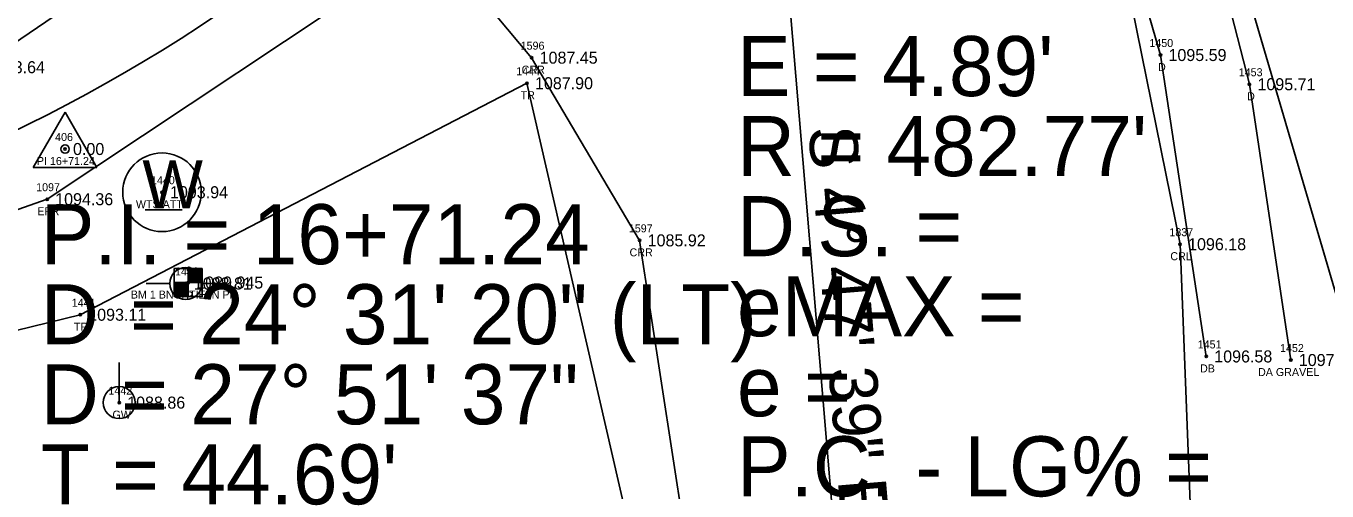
# Model space of a CAD drawing. Extents: x 1539151 to 1541799, y 1198646 to 1201165.
# Drawn here: x 1540056.1 to 1540218.7, y 1199362.7 to 1199420.8 of the extents above; entities that cross this region are included whole.
import ezdxf

# ---------------------------------------------------------------- set-up
doc = ezdxf.new("R2010")
doc.units = 0
for name, color, linetype in [('RD_EX_Driveway', 7, 'Continuous'), ('RD_EX_Driveway_txCode', 7, 'Continuous'), ('RD_EX_H2O', 7, 'Continuous'), ('RD_EX_H2O_txCode', 7, 'Continuous'), ('RD_EX_Road', 7, 'Continuous'), ('RD_EX_Road_txCode', 7, 'Continuous'), ('RD_EX_TX_Driveway_ELEV', 7, 'Continuous'), ('RD_EX_TX_H2O_ELEV', 7, 'Continuous'), ('RD_EX_TX_Road_ELEV', 7, 'Continuous'), ('RD_EX_TX_UT_ELEV', 7, 'Continuous'), ('RD_EX_TX_VEG_ELEV', 7, 'Continuous'), ('RD_EX_UT', 7, 'Continuous'), ('RD_EX_UT_txCode', 7, 'Continuous'), ('RD_EX_VEG', 7, 'Continuous'), ('RD_EX_VEG_txCode', 7, 'Continuous'), ('RD_HC_Cl', 7, 'Continuous'), ('RD_HC_Data', 7, 'Continuous'), ('RD_HC_Survey', 7, 'Continuous'), ('RD_HC_Survey_ELEV', 7, 'Continuous'), ('RD_HC_Survey_txCode', 7, 'Continuous'), ('RD_HC_txCode', 7, 'Continuous'), ('RD_SMD_Locator', 7, 'Continuous')]:
    doc.layers.add(name, color=color, linetype=linetype)

msp = doc.modelspace()

# ---------------------------------------------------------------- linework, layer by layer
at = {"layer": 'RD_EX_Driveway'}
for points in [[(1540214.21, 1199379.03), (1540209.04, 1199413.48), (1540199.66, 1199449.96), (1540186.8, 1199484.99), (1540182.78, 1199498.31), (1540181.23, 1199508.28)], [(1540167.88, 1199484.64), (1540174.25, 1199480.46), (1540187.6, 1199452.87), (1540197.92, 1199417.13), (1540203.64, 1199379.48)]]:
    msp.add_lwpolyline(points, dxfattribs=at)
at = {"layer": 'RD_EX_H2O'}
for points in [[(1540167.88, 1199484.64), (1540176.46, 1199458.2), (1540182.66, 1199452.12), (1540193.19, 1199429.05), (1540200.37, 1199393.5), (1540202.4, 1199340.71), (1540198.55, 1199306.73), (1540179.64, 1199280.12), (1540151.78, 1199264.65), (1540144.74, 1199262.14), (1540137.88, 1199248.47), (1540155.53, 1199232.49), (1540156.47, 1199194.6), (1540144.81, 1199166.15), (1540127.69, 1199133.28), (1540119.65, 1199099.79), (1540112.02, 1199051.08), (1540113.69, 1199004.24), (1540113.12, 1198937.28), (1540119.39, 1198871.63)], [(1540110.32, 1199427.56), (1540119.33, 1199416.8), (1540132.83, 1199393.98), (1540138.31, 1199358.3), (1540135.73, 1199340.81)]]:
    msp.add_lwpolyline(points, dxfattribs=at)
at = {"layer": 'RD_EX_Road'}
for points in [[(1539428.76, 1199454.93), (1539416.46, 1199395.23), (1539420.91, 1199377.84), (1539428.29, 1199368.53), (1539440.24, 1199363.06), (1539462.84, 1199364.11), (1539506.12, 1199366.59), (1539554.03, 1199368.02), (1539606.53, 1199370.48), (1539651.89, 1199372.76), (1539672.94, 1199372.91), (1539707.02, 1199374.85), (1539748.7, 1199377.62), (1539769.05, 1199378.19), (1539812.94, 1199380.16), (1539830.48, 1199381.23), (1539857.01, 1199382.87), (1539908.22, 1199385.45), (1539955.82, 1199389.74), (1539996.13, 1199397.4), (1540037.85, 1199410.51), (1540050.26, 1199415.61), (1540093.12, 1199444.78)], [(1539925.86, 1199367.85), (1539963.35, 1199372.53), (1539983.91, 1199375.76), (1540009.01, 1199381.59), (1540058.79, 1199399.12), (1540106.31, 1199430.72)]]:
    msp.add_lwpolyline(points, dxfattribs=at)
at = {"layer": 'RD_EX_UT'}
for p, q in [((1540071.02, 1199397.78), (1540075.65, 1199397.78)), ((1540071.18, 1199388.61), (1540074.11, 1199388.61)), ((1540078.11, 1199388.61), (1540081.18, 1199388.61)), ((1540067.79, 1199373.71), (1540067.79, 1199378.71))]:
    msp.add_line(p, q, dxfattribs=at)
for centre, radius in [((1540073.14, 1199399.99), 4.91), ((1540076.11, 1199388.59), 2), ((1540067.79, 1199373.71), 2)]:
    msp.add_circle(centre, radius, dxfattribs=at)
at = {"layer": 'RD_EX_VEG'}
for points in [[(1540836.37, 1200082.45), (1540794.45, 1200101.71), (1540758.65, 1200106.39), (1540697.29, 1200033.83), (1540560.39, 1199886.45), (1540422.51, 1199739.87), (1540382.08, 1199704.72), (1540267.52, 1199610.92), (1540233.68, 1199579.65), (1540209.33, 1199537.96), (1540187.75, 1199496.51), (1540221.64, 1199381.22)], [(1539913.28, 1199258.8), (1539924.81, 1199358.8), (1539963.86, 1199360.44), (1540062.92, 1199384.69), (1540118.75, 1199413.61), (1540135.27, 1199341.7), (1540089.61, 1199284.74)]]:
    msp.add_lwpolyline(points, dxfattribs=at)
at = {"layer": 'RD_HC_Cl'}
msp.add_line((1540150.21, 1199440.05), (1540160.06, 1199322.6), dxfattribs=at)
msp.add_arc((1539965.21, 1199592.77), 205.65, 284.8221, 309.3443, dxfattribs=at)
at = {"layer": 'RD_HC_Data'}
for p, q in [((1540057.05, 1199403.1), (1540061.03, 1199409.98)), ((1540061.03, 1199409.98), (1540064.99, 1199403.1)), ((1540057.05, 1199403.1), (1540064.99, 1199403.1))]:
    msp.add_line(p, q, dxfattribs=at)
msp.add_circle((1540061.02, 1199405.39), 0.529, dxfattribs=at)
at = {"layer": 'RD_HC_Survey'}
for p, q in [((1540076.42, 1199390.46), (1540076.42, 1199386.96)), ((1540076.44, 1199390.46), (1540076.44, 1199388.71)), ((1540076.46, 1199390.46), (1540076.46, 1199388.71)), ((1540076.49, 1199390.46), (1540076.49, 1199388.71)), ((1540076.51, 1199390.46), (1540076.51, 1199388.71)), ((1540076.54, 1199390.46), (1540076.54, 1199388.71)), ((1540076.56, 1199390.46), (1540076.56, 1199388.71)), ((1540076.59, 1199390.46), (1540076.59, 1199388.71)), ((1540076.61, 1199390.46), (1540076.61, 1199388.71)), ((1540076.64, 1199390.46), (1540076.64, 1199388.71)), ((1540076.66, 1199390.46), (1540076.66, 1199388.71)), ((1540076.69, 1199390.46), (1540076.69, 1199388.71)), ((1540076.71, 1199390.46), (1540076.71, 1199388.71)), ((1540076.74, 1199390.46), (1540076.74, 1199388.71)), ((1540076.76, 1199390.46), (1540076.76, 1199388.71)), ((1540076.79, 1199390.46), (1540076.79, 1199388.71)), ((1540076.81, 1199390.46), (1540076.81, 1199388.71)), ((1540076.83, 1199390.46), (1540076.83, 1199388.71)), ((1540076.86, 1199390.46), (1540076.86, 1199388.71)), ((1540076.88, 1199390.46), (1540076.88, 1199388.71)), ((1540076.91, 1199390.46), (1540076.91, 1199388.71)), ((1540076.93, 1199390.46), (1540076.93, 1199388.71)), ((1540076.96, 1199390.46), (1540076.96, 1199388.71)), ((1540076.98, 1199390.46), (1540076.98, 1199388.71)), ((1540077.01, 1199390.46), (1540077.01, 1199388.71)), ((1540077.03, 1199390.46), (1540077.03, 1199388.71)), ((1540077.06, 1199390.46), (1540077.06, 1199388.71)), ((1540077.08, 1199390.46), (1540077.08, 1199388.71)), ((1540077.11, 1199390.46), (1540077.11, 1199388.71)), ((1540077.13, 1199390.46), (1540077.13, 1199388.71)), ((1540077.16, 1199390.46), (1540077.16, 1199388.71)), ((1540077.18, 1199390.46), (1540077.18, 1199388.71)), ((1540077.21, 1199390.46), (1540077.21, 1199388.71)), ((1540077.23, 1199390.46), (1540077.23, 1199388.71)), ((1540077.26, 1199390.46), (1540077.26, 1199388.71)), ((1540077.28, 1199390.46), (1540077.28, 1199388.71)), ((1540077.3, 1199390.46), (1540077.3, 1199388.71)), ((1540077.33, 1199390.46), (1540077.33, 1199388.71)), ((1540077.35, 1199390.46), (1540077.35, 1199388.71)), ((1540077.38, 1199390.46), (1540077.38, 1199388.71)), ((1540077.4, 1199390.46), (1540077.4, 1199388.71)), ((1540077.43, 1199390.46), (1540077.43, 1199388.71)), ((1540077.45, 1199390.46), (1540077.45, 1199388.71)), ((1540077.48, 1199390.46), (1540077.48, 1199388.71)), ((1540077.5, 1199390.46), (1540077.5, 1199388.71)), ((1540077.53, 1199390.46), (1540077.53, 1199388.71)), ((1540077.55, 1199390.46), (1540077.55, 1199388.71)), ((1540077.58, 1199390.46), (1540077.58, 1199388.71)), ((1540077.6, 1199390.46), (1540077.6, 1199388.71)), ((1540077.63, 1199390.46), (1540077.63, 1199388.71)), ((1540077.65, 1199390.46), (1540077.65, 1199388.71)), ((1540077.68, 1199390.46), (1540077.68, 1199388.71)), ((1540077.7, 1199390.46), (1540077.7, 1199388.71)), ((1540077.73, 1199390.46), (1540077.73, 1199388.71)), ((1540077.75, 1199390.46), (1540077.75, 1199388.71)), ((1540077.78, 1199390.46), (1540077.78, 1199388.71)), ((1540077.8, 1199390.46), (1540077.8, 1199388.71)), ((1540077.82, 1199390.46), (1540077.82, 1199388.71)), ((1540077.85, 1199390.46), (1540077.85, 1199388.71)), ((1540077.87, 1199390.46), (1540077.87, 1199388.71)), ((1540077.9, 1199390.46), (1540077.9, 1199388.71)), ((1540077.92, 1199390.46), (1540077.92, 1199388.71)), ((1540077.95, 1199390.46), (1540077.95, 1199388.71)), ((1540077.97, 1199390.46), (1540077.97, 1199388.71)), ((1540078, 1199390.46), (1540078, 1199388.71)), ((1540078.02, 1199390.46), (1540078.02, 1199388.71)), ((1540078.05, 1199390.46), (1540078.05, 1199388.71)), ((1540078.07, 1199390.46), (1540078.07, 1199388.71)), ((1540078.1, 1199390.46), (1540078.1, 1199388.71)), ((1540078.12, 1199390.46), (1540078.12, 1199388.71)), ((1540078.15, 1199390.46), (1540078.15, 1199388.71)), ((1540078.17, 1199388.71), (1540074.67, 1199388.71)), ((1540074.67, 1199388.71), (1540074.67, 1199386.96)), ((1540074.7, 1199388.71), (1540074.7, 1199386.96)), ((1540074.72, 1199388.71), (1540074.72, 1199386.96)), ((1540074.75, 1199388.71), (1540074.75, 1199386.96)), ((1540074.77, 1199388.71), (1540074.77, 1199386.96)), ((1540074.79, 1199388.71), (1540074.79, 1199386.96)), ((1540074.82, 1199388.71), (1540074.82, 1199386.96)), ((1540074.84, 1199388.71), (1540074.84, 1199386.96)), ((1540074.87, 1199388.71), (1540074.87, 1199386.96)), ((1540074.89, 1199388.71), (1540074.89, 1199386.96)), ((1540074.92, 1199388.71), (1540074.92, 1199386.96)), ((1540074.94, 1199388.71), (1540074.94, 1199386.96)), ((1540074.97, 1199388.71), (1540074.97, 1199386.96)), ((1540074.99, 1199388.71), (1540074.99, 1199386.96)), ((1540075.02, 1199388.71), (1540075.02, 1199386.96)), ((1540075.04, 1199388.71), (1540075.04, 1199386.96)), ((1540075.07, 1199388.71), (1540075.07, 1199386.96)), ((1540075.09, 1199388.71), (1540075.09, 1199386.96)), ((1540075.12, 1199388.71), (1540075.12, 1199386.96)), ((1540075.14, 1199388.71), (1540075.14, 1199386.96)), ((1540075.17, 1199388.71), (1540075.17, 1199386.96)), ((1540075.19, 1199388.71), (1540075.19, 1199386.96)), ((1540075.22, 1199388.71), (1540075.22, 1199386.96)), ((1540075.24, 1199388.71), (1540075.24, 1199386.96)), ((1540075.27, 1199388.71), (1540075.27, 1199386.96)), ((1540075.29, 1199388.71), (1540075.29, 1199386.96)), ((1540075.31, 1199388.71), (1540075.31, 1199386.96)), ((1540075.34, 1199388.71), (1540075.34, 1199386.96)), ((1540075.36, 1199388.71), (1540075.36, 1199386.96)), ((1540075.39, 1199388.71), (1540075.39, 1199386.96)), ((1540075.41, 1199388.71), (1540075.41, 1199386.96)), ((1540075.44, 1199388.71), (1540075.44, 1199386.96)), ((1540075.46, 1199388.71), (1540075.46, 1199386.96)), ((1540075.49, 1199388.71), (1540075.49, 1199386.96)), ((1540075.51, 1199388.71), (1540075.51, 1199386.96)), ((1540075.54, 1199388.71), (1540075.54, 1199386.96)), ((1540075.56, 1199388.71), (1540075.56, 1199386.96)), ((1540075.59, 1199388.71), (1540075.59, 1199386.96)), ((1540075.61, 1199388.71), (1540075.61, 1199386.96)), ((1540075.64, 1199388.71), (1540075.64, 1199386.96)), ((1540075.66, 1199388.71), (1540075.66, 1199386.96)), ((1540075.69, 1199388.71), (1540075.69, 1199386.96)), ((1540075.71, 1199388.71), (1540075.71, 1199386.96)), ((1540075.74, 1199388.71), (1540075.74, 1199386.96)), ((1540075.76, 1199388.71), (1540075.76, 1199386.96)), ((1540075.78, 1199388.71), (1540075.78, 1199386.96)), ((1540075.81, 1199388.71), (1540075.81, 1199386.96)), ((1540075.83, 1199388.71), (1540075.83, 1199386.96)), ((1540075.86, 1199388.71), (1540075.86, 1199386.96)), ((1540075.88, 1199388.71), (1540075.88, 1199386.96)), ((1540075.91, 1199388.71), (1540075.91, 1199386.96)), ((1540075.93, 1199388.71), (1540075.93, 1199386.96)), ((1540075.96, 1199388.71), (1540075.96, 1199386.96)), ((1540075.98, 1199388.71), (1540075.98, 1199386.96)), ((1540076.01, 1199388.71), (1540076.01, 1199386.96)), ((1540076.03, 1199388.71), (1540076.03, 1199386.96)), ((1540076.06, 1199388.71), (1540076.06, 1199386.96)), ((1540076.08, 1199388.71), (1540076.08, 1199386.96)), ((1540076.11, 1199388.71), (1540076.11, 1199386.96)), ((1540076.13, 1199388.71), (1540076.13, 1199386.96)), ((1540076.16, 1199388.71), (1540076.16, 1199386.96)), ((1540076.18, 1199388.71), (1540076.18, 1199386.96)), ((1540076.21, 1199388.71), (1540076.21, 1199386.96)), ((1540076.23, 1199388.71), (1540076.23, 1199386.96)), ((1540076.26, 1199388.71), (1540076.26, 1199386.96)), ((1540076.28, 1199388.71), (1540076.28, 1199386.96)), ((1540076.3, 1199388.71), (1540076.3, 1199386.96)), ((1540076.33, 1199388.71), (1540076.33, 1199386.96)), ((1540076.35, 1199388.71), (1540076.35, 1199386.96)), ((1540076.38, 1199388.71), (1540076.38, 1199386.96)), ((1540076.4, 1199388.71), (1540076.4, 1199386.96))]:
    msp.add_line(p, q, dxfattribs=at)
msp.add_lwpolyline([(1540078.17, 1199390.46), (1540074.67, 1199390.46), (1540074.67, 1199386.96), (1540078.17, 1199386.96)], close=True, dxfattribs=at)
at = {"layer": 'RD_SMD_Locator'}
for centre in [(1540119.33, 1199416.8), (1540197.92, 1199417.13), (1540118.75, 1199413.61), (1540209.04, 1199413.48), (1540061.02, 1199405.39), (1540058.79, 1199399.12), (1540073.14, 1199399.99), (1540132.83, 1199393.98), (1540200.37, 1199393.5), (1540076.11, 1199388.59), (1540076.42, 1199388.71), (1540062.92, 1199384.69), (1540203.64, 1199379.48), (1540214.21, 1199379.03), (1540067.79, 1199373.71)]:
    msp.add_circle(centre, 0.15, dxfattribs=at)

# ---------------------------------------------------------------- texts
at = {"layer": 'RD_EX_Driveway_txCode'}
for s, p in [('1450', (1540196.53, 1199418.13)), ('D', (1540197.61, 1199415.13)), ('1453', (1540207.7, 1199414.48)), ('D', (1540208.74, 1199411.48)), ('1451', (1540202.57, 1199380.48)), ('1452', (1540212.86, 1199380.03)), ('DB', (1540202.86, 1199377.48)), ('DA GRAVEL', (1540210.11, 1199377.03))]:
    msp.add_text(s, height=1, dxfattribs=at).set_placement(p)
at = {"layer": 'RD_EX_H2O_txCode'}
for s, p in [('1596', (1540117.96, 1199417.8)), ('CRR', (1540118.08, 1199414.8)), ('1597', (1540131.48, 1199394.98)), ('1837', (1540199.03, 1199394.5)), ('CRR', (1540131.57, 1199391.98)), ('CRL', (1540199.15, 1199391.5))]:
    msp.add_text(s, height=1, dxfattribs=at).set_placement(p)
at = {"layer": 'RD_EX_Road_txCode'}
for s, p in [('1097', (1540057.41, 1199400.12)), ('EPR', (1540057.56, 1199397.12))]:
    msp.add_text(s, height=1, dxfattribs=at).set_placement(p)
at = {"layer": 'RD_EX_TX_Driveway_ELEV'}
for s, p in [('1095.59', (1540198.92, 1199416.38)), ('1095.71', (1540210.04, 1199412.73)), ('1096.58', (1540204.64, 1199378.73)), ('1097.29', (1540215.21, 1199378.28))]:
    msp.add_text(s, height=1.5, dxfattribs=at).set_placement(p)
at = {"layer": 'RD_EX_TX_H2O_ELEV'}
for s, p in [('1087.45', (1540120.33, 1199416.05)), ('1085.92', (1540133.83, 1199393.23)), ('1096.18', (1540201.37, 1199392.75))]:
    msp.add_text(s, height=1.5, dxfattribs=at).set_placement(p)
at = {"layer": 'RD_EX_TX_Road_ELEV'}
for s, p in [('1093.64', (1540051.26, 1199414.86)), ('1094.36', (1540059.79, 1199398.37))]:
    msp.add_text(s, height=1.5, dxfattribs=at).set_placement(p)
at = {"layer": 'RD_EX_TX_UT_ELEV'}
for s, p in [('1093.94', (1540074.14, 1199399.24)), ('1088.81', (1540077.11, 1199387.84)), ('1088.86', (1540068.79, 1199372.96))]:
    msp.add_text(s, height=1.5, dxfattribs=at).set_placement(p)
at = {"layer": 'RD_EX_TX_VEG_ELEV'}
for s, p in [('1087.90', (1540119.75, 1199412.86)), ('1093.11', (1540063.92, 1199383.94))]:
    msp.add_text(s, height=1.5, dxfattribs=at).set_placement(p)
at = {"layer": 'RD_EX_UT'}
msp.add_text('W', height=6, dxfattribs=at).set_placement((1540070.68, 1199397.99))
at = {"layer": 'RD_EX_UT_txCode'}
for s, p in [('1440', (1540071.76, 1199400.99)), ('WTS ATT', (1540069.88, 1199397.99)), ('1443', (1540074.77, 1199389.59)), ('TP', (1540075.32, 1199386.59)), ('1442', (1540066.44, 1199374.71)), ('GW', (1540066.95, 1199371.71))]:
    msp.add_text(s, height=1, dxfattribs=at).set_placement(p)
at = {"layer": 'RD_EX_VEG_txCode'}
for s, p in [('1444', (1540117.41, 1199414.61)), ('TR', (1540117.96, 1199411.61)), ('1441', (1540061.86, 1199385.69)), ('TR', (1540062.13, 1199382.69))]:
    msp.add_text(s, height=1, dxfattribs=at).set_placement(p)
at = {"layer": 'RD_HC_Data'}
for s, p in [("E = 4.89'", (1540145, 1199412)), ("R = 482.77'", (1540145, 1199402)), ('D.S. = ', (1540145, 1199392)), ('P.I. = 16+71.24', (1540058, 1199391)), ('eMAX = ', (1540145, 1199382)), ('D', (1540058, 1199381)), ('    = 24%%d 31\' 20" (LT)', (1540058, 1199381)), ('D = 27%%d 51\' 37"', (1540058, 1199371)), ('e = ', (1540145, 1199372)), ("T = 44.69'", (1540058, 1199361)), ('P.C. - LG% = ', (1540145, 1199362))]:
    msp.add_text(s, height=7.5, dxfattribs=at).set_placement(p)
msp.add_text('S 4%%d 47\' 39" E', height=6, rotation=274.7943, dxfattribs=at).set_placement((1540153.9, 1199408.03))
at = {"layer": 'RD_HC_Survey_ELEV'}
for s, p in [('0.00', (1540062.02, 1199404.64)), ('1089.945', (1540077.42, 1199387.96))]:
    msp.add_text(s, height=1.5, dxfattribs=at).set_placement(p)
at = {"layer": 'RD_HC_Survey_txCode'}
for s, p in [('9', (1540076.14, 1199389.71)), ('BM 1 BNCHTIE IN PP', (1540069.24, 1199386.71))]:
    msp.add_text(s, height=1, dxfattribs=at).set_placement(p)
at = {"layer": 'RD_HC_txCode'}
for s, p in [('406', (1540059.78, 1199406.39)), ('PI 16+71.24', (1540057.5, 1199403.39))]:
    msp.add_text(s, height=1, dxfattribs=at).set_placement(p)

doc.saveas('drawing.dxf')
